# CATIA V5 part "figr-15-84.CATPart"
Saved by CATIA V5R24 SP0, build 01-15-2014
Part number: Part1
Bounding box of the stored display mesh (mm): x 0 to 27, y -46 to 46, z -30 to 30
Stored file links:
  D:\KAVITA\CATIA V5-6R2014 Project_ Kavita\CATIA V5-6R2014_partfiles\Partfiles\c15_catia_v5-6r2014_prt\figr-15-84.CATPart
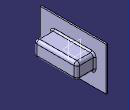
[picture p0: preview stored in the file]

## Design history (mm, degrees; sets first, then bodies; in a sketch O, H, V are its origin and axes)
SheetMetalParameters1: Thickness 2, BendRadius 4, ReliefRadialLength 1, KFactor 0.400515 {= log(min(100,max(20*SheetMetalParameters1.BendRadius,SheetMetalParameters1.Thickness)/SheetMetalParameters1.Thickness))/log(100)/2}, ReliefAxialLength 2, MinimumBendRadius 0
Body1 (main body)
  Sketch1 on yz-plane, origin (0, 0, 0), H (0, 1, 0), V (0, 0, 1)
    line L1 (46, 30) -> (46, -30)
    line L2 (46, -30) -> (-46, -30)
    line L3 (-46, -30) -> (-46, 30)
    line L4 (-46, 30) -> (46, 30)
    vertical: L1 V, L3 V
    horizontal: L2 H, L4 H
    equidistance: L1 L3 O, L2 L4 O
  Wall1: Thickness 2, Profile Sketch1, OffsetValue 0
  Sketch2 on face of Wall1, origin (2, 0, 0), H (0, 1, 0), V (0, 0, 1)
    line L1 (28, 9) -> (28, -9)
    line L2 (28, -9) -> (-28, -9)
    line L3 (-28, -9) -> (-28, 9)
    line L4 (-28, 9) -> (28, 9)
    vertical: L1 V, L3 V
    horizontal: L2 H, L4 H
    equidistance: L1 L3 O, L2 L4 O
  d_Stamp1: NewRoot_AttribNormalisation "No Standard", Stamp_FilletRadius 2, Stamp_IntersectFilletRadius 2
